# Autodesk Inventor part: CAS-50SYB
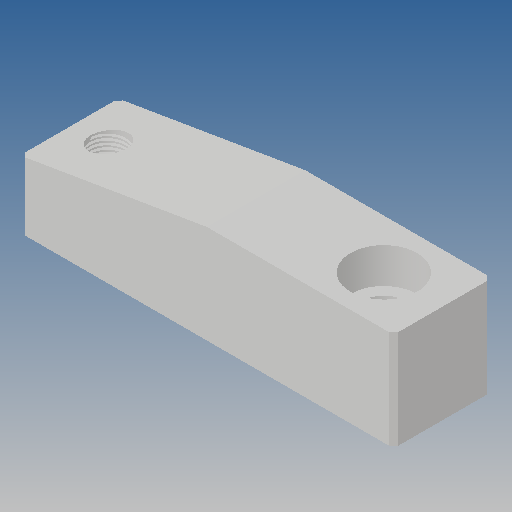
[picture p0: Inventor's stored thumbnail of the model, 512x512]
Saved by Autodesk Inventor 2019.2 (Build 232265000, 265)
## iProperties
Created: 2009-09
Part Number: CAS-50SYB
Material: Ogólny
Document SubType Name: Modeling
Designer: CADENGINEERING4
Density: 1 g/cm^3
Appearance: Domyślna
Author: CADENGINEERING4
Revision Number: 1LAST_VERSION
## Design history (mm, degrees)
feature "Baza1"
node "Bryła1"
